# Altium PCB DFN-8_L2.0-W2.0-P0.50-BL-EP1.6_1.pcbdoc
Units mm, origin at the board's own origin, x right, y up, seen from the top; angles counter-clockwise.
Board outline 14.85 x 15.45 mm, 2 copper layers (Top Layer, Bottom Layer), stack 0 mm thick; 1 components, 0 nets, 9 pads, 0 vias.
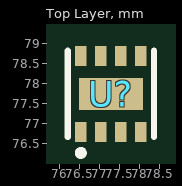
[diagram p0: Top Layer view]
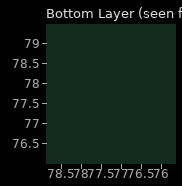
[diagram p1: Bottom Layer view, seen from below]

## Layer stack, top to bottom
Top Layer: signal copper (thickness not stored)
Bottom Layer: signal copper (thickness not stored)

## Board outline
84.702,69.85 69.85,69.85 69.85,85.305 84.702,85.305

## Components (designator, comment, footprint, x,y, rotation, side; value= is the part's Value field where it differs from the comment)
U? "" DFN-8_L2.0-W2.0-P0.50-BL-EP1.6_1 77.276,77.755 r0 top

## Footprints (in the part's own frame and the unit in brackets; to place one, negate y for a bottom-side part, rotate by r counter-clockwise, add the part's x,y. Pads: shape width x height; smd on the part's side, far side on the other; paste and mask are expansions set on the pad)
DFN-8_L2.0-W2.0-P0.50-BL-EP1.6_1 [mm]
  rect 0.28x0.5 smd paste+0 mask+0.05: 1(-0.75,-0.95) 2(-0.25,-0.95) 3(0.25,-0.95) 4(0.75,-0.95) 5(0.75,0.95) 6(0.25,0.95) 7(-0.25,0.95) 8(-0.75,0.95)
  rect 1.6x0.8 smd paste+0 mask+0.05: 9(0,0)
  silkscreen extent -1.08,-1.55 1.08,1.08

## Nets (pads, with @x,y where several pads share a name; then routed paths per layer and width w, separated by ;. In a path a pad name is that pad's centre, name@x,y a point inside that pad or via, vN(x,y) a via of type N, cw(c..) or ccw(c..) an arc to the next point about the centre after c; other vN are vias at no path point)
pads on no net: U?.1 U?.2 U?.3 U?.4 U?.5 U?.6 U?.7 U?.8 U?.9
